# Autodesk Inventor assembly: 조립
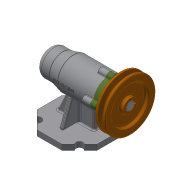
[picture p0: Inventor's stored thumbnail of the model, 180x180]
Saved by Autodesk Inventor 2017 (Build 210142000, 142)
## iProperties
Created: 2019-12
Part Number: 조립
Document SubType Name: Assembly
Designer: 5-13-le-1
Author: 5-13-le-1
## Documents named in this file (12)
- C:\Users\5-13-le-1\Desktop\491204V1004\조립.iam
- C:\Users\5-13-le-1\Desktop\491204V1004\1.ipt
- C:\Users\5-13-le-1\Desktop\491204V1004\키 5 x 5 x 16.ipt
- C:\Users\5-13-le-1\Desktop\491204V1004\V벨트풀리.ipt
- C:\Users\5-13-le-1\Desktop\491204V1004\멈춤나사 M3.ipt
- C:\Users\5-13-le-1\Desktop\491204V1004\베어링 6004.ipt
- C:\Users\5-13-le-1\Desktop\491204V1004\베어링 51202.ipt
- C:\Users\5-13-le-1\Desktop\491204V1004\볼트 M4.ipt
- C:\Users\5-13-le-1\Desktop\491204V1004\어댑터슬리브.ipt
- C:\Users\5-13-le-1\Desktop\491204V1004\오일 실.ipt
- C:\Users\5-13-le-1\Desktop\491204V1004\축.ipt
- C:\Users\5-13-le-1\Desktop\491204V1004\커버.ipt
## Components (2 placed, 2 different names)
1. 1:1 — 플러쉬:1, 플러쉬:2, 플러쉬:3
2. V벨트풀리:1
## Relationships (3: Flush 3)
- 플러쉬:1 [Flush]: 1:1
- 플러쉬:2 [Flush]: 1:1
- 플러쉬:3 [Flush]: 1:1
